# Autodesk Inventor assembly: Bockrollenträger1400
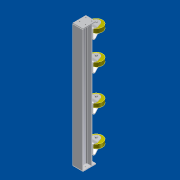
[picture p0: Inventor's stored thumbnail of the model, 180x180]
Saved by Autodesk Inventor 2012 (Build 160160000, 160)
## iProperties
Company: CAD-Verlag
Shininess: 64.0
Length Units: 11269
Angle Units: 11279
Time Units: 11290
Mass Units: 11283
Length Display Precision: 3
Angle Display Precision: 2
Compacted: True
Created: 2004-09
Part Number: Bockrollenträger1400
Document SubType Name: Assembly
Designer: Greiling
Manufacturer: Standard
Standards Organization: Custom
Density: 0.0
Volumn: 0.0
Area: 0.0
PropertySet Name: Model Information
Control State: 0
Master: False
Checked Out: False
Author: Jürgen Kronas
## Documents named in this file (4)
- C:\DemoDaten2012\CAD Daten\Daten Vault 2012 Inventor\Kapitel 6\6.4\Rollenbahn\Rollenbahn 1400\Bockrollenträger1400.iam
- C:\DemoDaten2012\CAD Daten\Daten Vault 2012 Inventor\Kapitel 6\6.4\Rollenbahn\Rollenbahn 1400\IPBl120_1467.ipt
- C:\DemoDaten2012\CAD Daten\Daten Vault 2012 Inventor\Kapitel 6\6.4\Rollenbahn\Rollenbahn 1400\0498904.ipt
- C:\DemoDaten2012\CAD Daten\Daten Vault 2012 Inventor\Kapitel 6\6.4\Rollenbahn\Rollenbahn 1400\Bockrolle.iam
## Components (7 placed, 3 different names)
1. IPBl120_1467:1 — Fluchtend:1, Passend:1, Fluchtend:2, Passend:2, Fluchtend:3, Fluchtend:4, Fluchtend:5, Passend:3, Passend:5
2. 0498904:1 — Fluchtend:1, Passend:1, Fluchtend:2, Passend:4, Passend:6
3. 0498904:2 — Passend:2, Fluchtend:3, Fluchtend:4
4. Bockrolle:4 [sub-assembly] — Passend:5, Passend:6
5. Bockrolle:1 [sub-assembly] — Fluchtend:5, Passend:3, Passend:4
6. Bockrolle:2 [sub-assembly]
7. Bockrolle:3 [sub-assembly]
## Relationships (11: Mate 6, Flush 5)
- Fluchtend:1 [Flush]: IPBl120_1467:1 ↔ 0498904:1
- Passend:1 [Mate]: IPBl120_1467:1 ↔ 0498904:1
- Fluchtend:2 [Flush]: IPBl120_1467:1 ↔ 0498904:1
- Passend:2 [Mate]: IPBl120_1467:1 ↔ 0498904:2
- Fluchtend:3 [Flush]: IPBl120_1467:1 ↔ 0498904:2
- Fluchtend:4 [Flush]: IPBl120_1467:1 ↔ 0498904:2
- Fluchtend:5 [Flush]: IPBl120_1467:1 ↔ Bockrolle:1
- Passend:3 [Mate]: IPBl120_1467:1 ↔ Bockrolle:1
- Passend:4 [Mate]: 0498904:1 ↔ Bockrolle:1
- Passend:5 [Mate]: IPBl120_1467:1 ↔ Bockrolle:4
- Passend:6 [Mate]: 0498904:1 ↔ Bockrolle:4
